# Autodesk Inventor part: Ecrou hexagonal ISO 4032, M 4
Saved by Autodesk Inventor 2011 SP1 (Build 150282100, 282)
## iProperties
Created: 2010-12
Part Number: Ecrou hexagonal ISO 4032, M 4
Document SubType Name: Modeling
Designer: eric
Density: 1 g/cm^3
Author: eric
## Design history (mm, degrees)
feature "Base1"
node "Solide1"
node "Corps solides"
node "Corps surfaciques"
